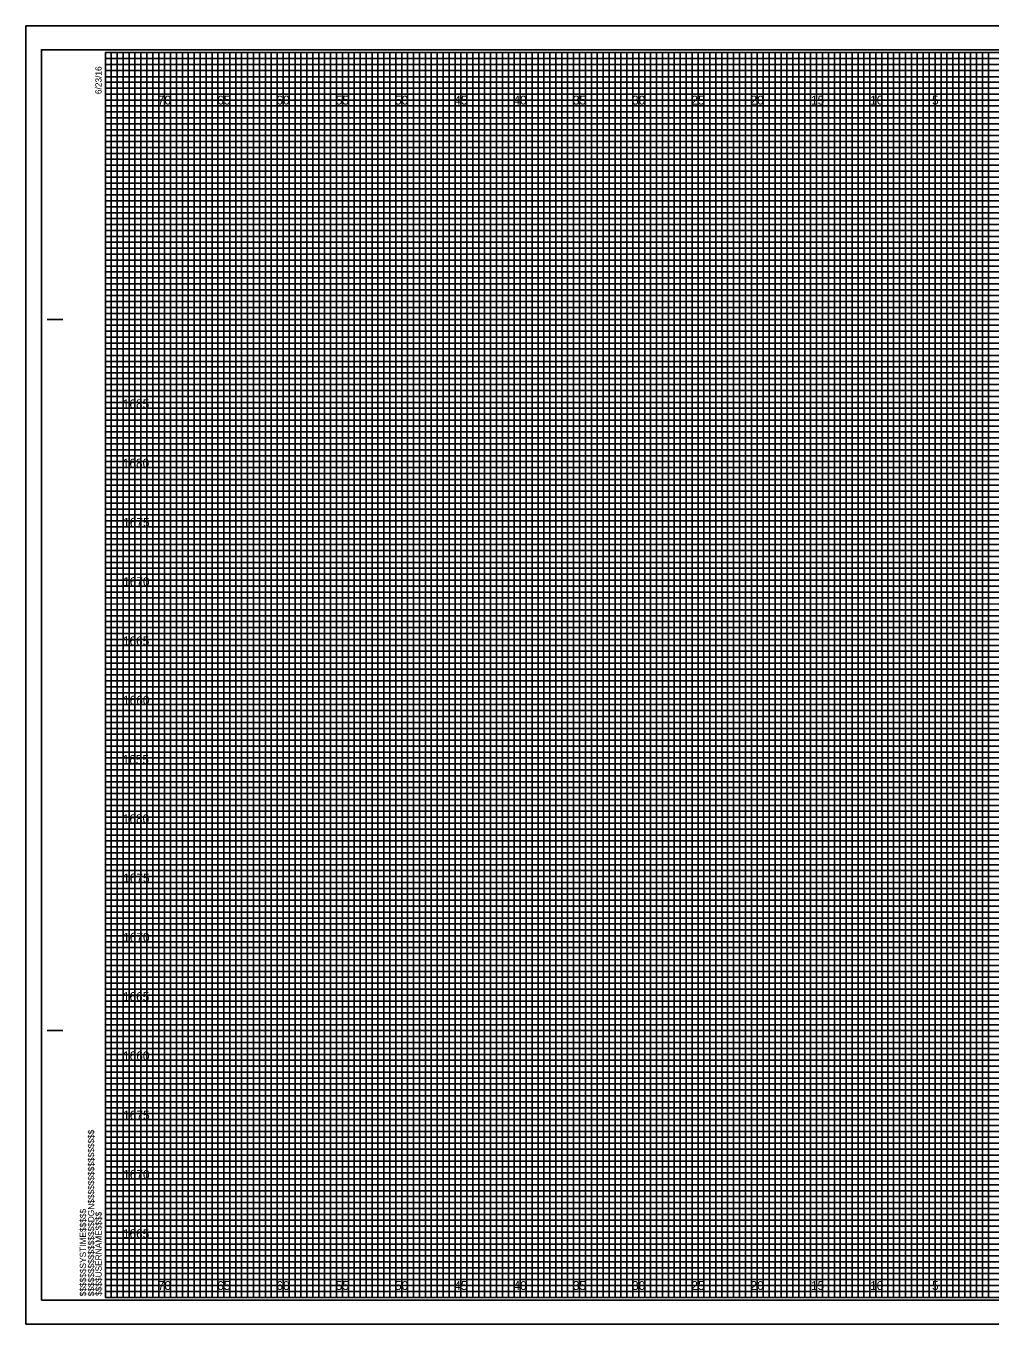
# Model space of a CAD drawing. Extents: x 172 to 723, y -2 to 439.
# Drawn here: x 172.3 to 253.6, y -2.3 to 107.3 of the extents above; entities that cross this region are included whole.
import ezdxf

# ---------------------------------------------------------------- set-up
doc = ezdxf.new("R2010")
doc.units = 0
for name, color, linetype in [('Prop XS Elevation Labels', 7, 'Continuous'), ('Prop XS Offset Labels', 7, 'Continuous'), ('Sheet Cross Section CELL', 7, 'Continuous'), ('Sheet Cross Section Grid Major CELL', 7, 'Continuous'), ('Sheet Cross Section Grid Middle CELL', 7, 'Continuous'), ('Sheet Cross Section Grid Minor 1 CELL', 7, 'Continuous'), ('Sheet Cross Section Grid Minor 2 CELL', 7, 'Continuous'), ('Sheet Cutting Line CELL', 7, 'Continuous'), ('Sheet DOT Grid CELL', 7, 'Continuous'), ('Sheet Plot Border Inside CELL', 7, 'Continuous'), ('Sheet Plot Border Outside CELL', 7, 'Continuous')]:
    doc.layers.add(name, color=color, linetype=linetype)

msp = doc.modelspace()

# ---------------------------------------------------------------- linework, layer by layer
at = {"layer": 'Sheet Cross Section CELL'}
for p, q in [((174.07, 82.5), (175.32, 82.5)), ((174.12, 82.5), (175.37, 82.5)), ((174.07, 22.5), (175.32, 22.5)), ((174.12, 22.5), (175.37, 22.5)), ((178.97, 0), (178.97, 0)), ((178.97, 0), (178.97, 0)), ((178.97, 0), (178.97, 0)), ((178.97, 0), (178.97, 0)), ((178.97, 0), (178.97, 0)), ((178.97, 0), (178.97, 0)), ((178.97, 0), (178.97, 0))]:
    msp.add_line(p, q, dxfattribs=at)
msp.add_lwpolyline([(338.97, 105), (178.97, 105), (178.97, 0), (338.97, 0)], close=True, dxfattribs=at)
at = {"layer": 'Sheet Cross Section Grid Major CELL'}
for p, q in [((183.97, 105), (178.97, 105)), ((183.97, 0), (183.97, 105)), ((193.97, 105), (188.97, 105)), ((188.97, 105), (188.97, 0)), ((193.97, 0), (193.97, 105)), ((203.97, 105), (198.97, 105)), ((198.97, 105), (198.97, 0)), ((203.97, 0), (203.97, 105)), ((213.97, 105), (208.97, 105)), ((208.97, 105), (208.97, 0)), ((213.97, 0), (213.97, 105)), ((223.97, 105), (218.97, 105)), ((218.97, 105), (218.97, 0)), ((223.97, 0), (223.97, 105)), ((233.97, 105), (228.97, 105)), ((228.97, 105), (228.97, 0)), ((233.97, 0), (233.97, 105)), ((243.97, 105), (238.97, 105)), ((238.97, 105), (238.97, 0)), ((243.97, 0), (243.97, 105)), ((253.97, 105), (248.97, 105)), ((248.97, 105), (248.97, 0)), ((188.97, 0), (183.97, 0)), ((198.97, 0), (193.97, 0)), ((208.97, 0), (203.97, 0)), ((218.97, 0), (213.97, 0)), ((228.97, 0), (223.97, 0)), ((238.97, 0), (233.97, 0)), ((248.97, 0), (243.97, 0))]:
    msp.add_line(p, q, dxfattribs=at)
for points in [[(178.97, 100), (338.97, 100), (338.97, 95), (178.97, 95)], [(178.97, 90), (338.97, 90), (338.97, 85), (178.97, 85)], [(178.97, 80), (338.97, 80), (338.97, 75), (178.97, 75)], [(178.97, 70), (338.97, 70), (338.97, 65), (178.97, 65)], [(178.97, 60), (338.97, 60), (338.97, 55), (178.97, 55)], [(178.97, 50), (338.97, 50), (338.97, 45), (178.97, 45)], [(178.97, 40), (338.97, 40), (338.97, 35), (178.97, 35)], [(178.97, 30), (338.97, 30), (338.97, 25), (178.97, 25)], [(178.97, 20), (338.97, 20), (338.97, 15), (178.97, 15)], [(178.97, 10), (338.97, 10), (338.97, 5), (178.97, 5)]]:
    msp.add_lwpolyline(points, dxfattribs=at)
at = {"layer": 'Sheet Cross Section Grid Middle CELL'}
for points in [[(178.97, 105), (181.47, 105), (181.47, 0), (186.47, 0), (186.47, 105), (191.47, 105), (191.47, 0), (196.47, 0), (196.47, 105), (201.47, 105), (201.47, 0), (206.47, 0), (206.47, 105), (211.47, 105), (211.47, 0), (216.47, 0), (216.47, 105), (221.47, 105), (221.47, 0), (226.47, 0), (226.47, 105), (231.47, 105), (231.47, 0), (236.47, 0), (236.47, 105), (241.47, 105), (241.47, 0), (246.47, 0), (246.47, 105), (251.47, 105), (251.47, 0), (256.47, 0)], [(178.97, 102.5), (316.47, 102.5)], [(178.97, 92.5), (338.97, 92.5), (338.97, 97.5), (178.97, 97.5)], [(178.97, 82.5), (338.97, 82.5), (338.97, 87.5), (178.97, 87.5)], [(178.97, 72.5), (338.97, 72.5), (338.97, 77.5), (178.97, 77.5)], [(178.97, 62.5), (338.97, 62.5), (338.97, 67.5), (178.97, 67.5)], [(178.97, 52.5), (338.97, 52.5), (338.97, 57.5), (178.97, 57.5)], [(178.97, 42.5), (338.97, 42.5), (338.97, 47.5), (178.97, 47.5)], [(178.97, 32.5), (338.97, 32.5), (338.97, 37.5), (178.97, 37.5)], [(178.97, 22.5), (338.97, 22.5), (338.97, 27.5), (178.97, 27.5)], [(178.97, 12.5), (338.97, 12.5), (338.97, 17.5), (178.97, 17.5)], [(178.97, 2.5), (338.97, 2.5), (338.97, 7.5), (178.97, 7.5)]]:
    msp.add_lwpolyline(points, dxfattribs=at)
at = {"layer": 'Sheet Cross Section Grid Minor 1 CELL'}
for p, q in [((178.97, 104.5), (308.97, 104.5)), ((308.97, 103.99), (178.97, 103.99)), ((178.97, 103.99), (178.97, 103.5)), ((178.97, 103.5), (308.97, 103.5)), ((308.97, 102.95), (178.97, 102.95)), ((178.97, 102.95), (178.97, 102)), ((178.97, 102), (338.97, 102))]:
    msp.add_line(p, q, dxfattribs=at)
for points in [[(178.97, 101.5), (313.97, 101.5), (338.97, 101.5), (338.97, 101), (178.97, 101)], [(178.97, 100.5), (338.97, 100.5), (338.97, 99.5), (178.97, 99.5)], [(178.97, 99), (338.97, 99), (338.97, 98.5), (178.97, 98.49)], [(178.97, 98), (338.97, 98), (338.97, 97), (178.97, 97)], [(178.97, 96.5), (338.97, 96.5), (338.97, 96), (178.97, 96)], [(178.97, 95.5), (338.97, 95.5), (338.97, 94.5), (178.97, 94.5)], [(178.97, 94), (338.97, 94), (338.97, 93.5), (178.97, 93.5)], [(178.97, 93), (338.97, 93), (338.97, 92), (178.97, 92)], [(178.97, 91.5), (338.97, 91.5), (338.97, 91), (178.97, 91)], [(178.97, 90.5), (338.97, 90.5), (338.97, 89.5), (178.97, 89.5)], [(178.97, 89), (338.97, 89), (338.97, 88.5), (178.97, 88.5)], [(178.97, 88), (338.97, 88), (338.97, 86.98), (338.97, 86.5), (338.97, 86), (178.97, 86)], [(178.97, 87), (338.97, 87), (338.97, 86.5), (178.97, 86.5)], [(178.97, 85.5), (338.97, 85.5), (338.97, 84.5), (178.97, 84.52)], [(178.97, 84.52), (338.97, 84.5), (338.97, 84), (178.97, 84)], [(178.97, 83.5), (338.97, 83.5), (338.97, 83), (178.97, 83)], [(178.97, 82), (338.97, 82), (338.97, 81.5), (178.97, 81.5)], [(178.97, 81), (338.97, 81), (338.97, 80.5), (178.97, 80.5)], [(178.94, 79.45), (338.97, 79.45), (338.97, 78.94), (178.94, 78.94)], [(178.97, 78.5), (338.97, 78.5), (338.97, 78), (178.97, 78)], [(178.97, 77), (338.97, 77), (338.97, 76.5), (178.97, 76.5)], [(178.97, 76), (338.97, 76), (338.97, 75.5), (178.97, 75.5)], [(178.97, 74.5), (338.97, 74.5), (338.97, 74), (178.97, 74)], [(178.97, 73.5), (338.97, 73.5), (338.97, 73), (178.97, 73)], [(178.97, 72), (338.97, 72), (338.97, 71.5), (178.97, 71.5)], [(178.97, 71), (338.97, 71), (338.97, 70.5), (178.97, 70.5)], [(178.97, 69.5), (338.97, 69.5), (338.97, 68.99), (178.97, 69)], [(178.97, 68.5), (338.97, 68.5), (338.97, 68), (178.97, 68)], [(178.97, 67), (338.97, 67), (338.97, 66.5), (178.97, 66.5)], [(178.97, 66), (338.97, 66), (338.97, 65.5), (178.97, 65.5)], [(178.97, 64.5), (338.97, 64.5), (338.97, 64), (178.97, 64)], [(178.97, 63.5), (338.97, 63.5), (338.97, 63), (178.97, 63)], [(178.97, 62), (338.97, 62), (338.97, 61.5), (178.97, 61.5)], [(178.97, 61), (338.97, 61), (338.97, 60.5), (178.97, 60.5)], [(178.97, 59.5), (338.97, 59.5), (338.97, 59), (178.97, 59)], [(178.97, 58.5), (339.01, 58.45), (338.97, 58), (178.97, 58)], [(178.97, 57), (338.97, 57), (338.97, 56.5), (178.97, 56.5)], [(178.97, 56), (338.97, 56), (338.97, 55.5), (178.97, 55.5)], [(178.97, 54.5), (338.97, 54.5), (338.97, 54), (178.97, 54)], [(178.97, 53.5), (338.97, 53.5), (338.97, 53), (178.97, 53)], [(178.97, 52), (338.97, 52), (338.97, 51.5), (178.97, 51.5)], [(178.97, 51), (338.97, 51), (338.97, 50.5), (178.97, 50.5)], [(178.97, 49.5), (338.97, 49.5), (338.97, 49), (178.97, 49)], [(178.97, 48.5), (338.97, 48.5), (338.97, 48), (178.97, 48)], [(178.97, 47), (338.97, 47), (338.97, 46.5), (178.97, 46.5)], [(178.97, 46), (338.97, 46), (338.97, 45.5), (178.97, 45.5)], [(178.97, 44.5), (338.97, 44.5), (338.97, 44), (178.97, 44)], [(178.97, 43.5), (338.97, 43.5), (338.97, 43), (178.97, 43)], [(178.97, 42), (338.97, 42), (338.97, 41.5), (178.97, 41.5)], [(178.97, 41), (338.97, 41), (338.97, 40.5), (178.97, 40.5)], [(178.97, 39.5), (338.97, 39.5), (338.97, 38.99), (178.97, 39)], [(178.97, 38.5), (338.97, 38.5), (338.97, 38), (178.97, 38)], [(178.97, 37), (338.97, 37), (338.97, 36.5), (178.97, 36.5)], [(178.97, 36), (338.97, 36), (338.97, 35.5), (178.97, 35.5)], [(178.97, 34.5), (338.97, 34.5), (338.97, 34), (178.97, 34)], [(178.97, 33.5), (338.97, 33.5), (338.97, 33), (178.97, 33)], [(178.97, 32), (338.97, 32), (338.97, 31.5), (178.97, 31.5)], [(178.97, 31), (338.97, 31), (338.97, 30.5), (178.97, 30.5)], [(178.97, 29.5), (338.97, 29.5), (338.97, 29), (178.97, 29)], [(178.97, 28.5), (339.01, 28.46), (338.97, 28), (178.97, 28)], [(178.97, 27), (338.97, 27), (338.97, 26.5), (178.97, 26.5)], [(178.97, 26), (338.97, 26), (338.97, 25.5), (178.97, 25.5)], [(178.97, 24.5), (338.97, 24.5), (338.97, 24), (178.97, 24)], [(178.97, 23.5), (338.97, 23.5), (338.97, 23), (178.97, 23)], [(178.97, 22), (338.97, 22), (338.97, 21.5), (178.97, 21.5)], [(178.97, 21), (338.97, 21), (338.97, 20.5), (178.97, 20.5)], [(178.97, 19.5), (338.97, 19.5), (338.97, 19), (178.97, 19)], [(178.97, 18.5), (338.97, 18.5), (338.97, 18), (178.97, 18)], [(178.97, 17), (338.97, 17), (338.97, 16.5), (178.97, 16.5)], [(178.97, 16), (338.97, 16), (338.97, 15.5), (178.97, 15.5)], [(178.97, 14.5), (338.97, 14.5), (338.97, 14), (178.97, 14)], [(178.97, 13.5), (338.97, 13.5), (338.97, 13), (178.97, 13)], [(178.97, 12), (338.97, 12), (338.97, 11.5), (178.97, 11.5)], [(178.97, 11), (338.97, 11), (338.97, 10.5), (178.97, 10.5)], [(178.97, 9.5), (338.97, 9.5), (338.97, 9), (178.97, 9)], [(178.97, 8.5), (338.97, 8.5), (338.97, 8), (178.97, 8)], [(178.97, 7), (338.97, 7), (338.97, 6.5), (178.97, 6.5)], [(178.97, 6), (338.97, 6), (338.97, 5.5), (178.97, 5.5)], [(178.97, 4.5), (338.97, 4.5), (338.97, 4), (178.97, 4)], [(178.97, 3.5), (338.97, 3.5), (338.97, 3), (178.97, 3)], [(178.97, 2), (338.97, 2), (338.97, 1.5), (178.97, 1.5)], [(178.97, 1), (338.97, 1), (338.97, 0.5), (178.97, 0.5)]]:
    msp.add_lwpolyline(points, dxfattribs=at)
at = {"layer": 'Sheet Cross Section Grid Minor 2 CELL'}
for points in [[(178.97, 0), (179.47, 0), (179.47, 105), (179.97, 105), (179.97, 0)], [(179.97, 0), (180.47, 0), (180.47, 105), (180.97, 105), (180.97, 0)], [(181.47, 0), (181.97, 0), (181.97, 105), (182.47, 105), (182.47, 0)], [(182.47, 0), (182.97, 0), (182.97, 105), (183.47, 105), (183.47, 0)], [(183.97, 0), (184.47, 0), (184.47, 105), (184.97, 105), (184.97, 0)], [(184.97, 0), (185.47, 0), (185.47, 105), (185.97, 105), (185.97, 0)], [(186.47, 0), (186.97, 0), (186.97, 105), (187.47, 105), (187.47, 0)], [(187.47, 0), (187.97, 0), (187.97, 105), (188.47, 105), (188.47, 0)], [(188.97, 0), (189.47, 0), (189.47, 105), (189.97, 105), (189.97, 0)], [(189.97, 0), (190.47, 0), (190.47, 105), (190.97, 105), (190.97, 0)], [(191.47, 0), (191.97, 0), (191.97, 105), (192.47, 105), (192.47, 0)], [(192.47, 0), (192.97, 0), (192.97, 105), (193.47, 105), (193.47, 0)], [(193.97, 0), (194.47, 0), (194.47, 105), (194.97, 105), (194.97, 0)], [(194.97, 0), (195.47, 0), (195.47, 105), (195.97, 105), (195.97, 0)], [(196.47, 0), (196.97, 0), (196.97, 105), (197.47, 105), (197.47, 0)], [(197.47, 0), (197.97, 0), (197.97, 105), (198.47, 105), (198.47, 0)], [(198.97, 0), (199.47, 0), (199.47, 105), (199.97, 105), (199.97, 0)], [(199.97, 0), (200.47, 0), (200.47, 105), (200.97, 105), (200.97, 0)], [(201.47, 0), (201.97, 0), (201.97, 105), (202.47, 105), (202.47, 0)], [(202.47, 0), (202.97, 0), (202.97, 105), (203.47, 105), (203.47, 0)], [(203.97, 0), (204.47, 0), (204.47, 105), (204.97, 105), (204.97, 0)], [(204.97, 0), (205.47, 0), (205.47, 105), (205.97, 105), (205.97, 0)], [(206.47, 0), (206.97, 0), (206.97, 105), (207.47, 105), (207.47, 0)], [(207.47, 0), (207.97, 0), (207.97, 105), (208.47, 105), (208.47, 0)], [(208.97, 0), (209.47, 0), (209.47, 105), (209.97, 105), (209.97, 0)], [(209.97, 0), (210.47, 0), (210.47, 105), (210.97, 105), (210.97, 0)], [(211.47, 0), (211.97, 0), (211.97, 105), (212.47, 105), (212.47, 0)], [(212.47, 0), (212.97, 0), (212.97, 105), (213.47, 105), (213.47, 0)], [(213.97, 0), (214.47, 0), (214.47, 105), (214.97, 105), (214.97, 0)], [(214.97, 0), (215.47, 0), (215.47, 105), (215.97, 105), (215.97, 0)], [(216.47, 0), (216.97, 0), (216.97, 105), (217.47, 105), (217.47, 0)], [(217.47, 0), (217.97, 0), (217.97, 105), (218.47, 105), (218.47, 0)], [(218.97, 0), (219.47, 0), (219.47, 105), (219.97, 105), (219.97, 0)], [(219.97, 0), (220.47, 0), (220.47, 105), (220.97, 105), (220.97, 0)], [(221.47, 0), (221.97, 0), (221.97, 105), (222.47, 105), (222.47, 0)], [(222.47, 0), (222.97, 0), (222.97, 105), (223.47, 105), (223.47, 0)], [(223.97, 0), (224.47, 0), (224.47, 105), (224.97, 105), (224.97, 0)], [(224.97, 0), (225.47, 0), (225.47, 105), (225.97, 105), (225.97, 0)], [(226.47, 0), (226.97, 0), (226.97, 105), (227.47, 105), (227.47, 0)], [(227.47, 0), (227.97, 0), (227.97, 105), (228.47, 105), (228.47, 0)], [(228.97, 0), (229.47, 0), (229.47, 105), (229.97, 105), (229.97, 0)], [(229.97, 0), (230.47, 0), (230.47, 105), (230.97, 105), (230.97, 0)], [(231.47, 0), (231.97, 0), (231.97, 105), (232.47, 105), (232.47, 0)], [(232.47, 0), (232.97, 0), (232.97, 105), (233.47, 105), (233.47, 0)], [(233.97, 0), (234.47, 0), (234.47, 105), (234.97, 105), (234.97, 0)], [(234.97, 0), (235.47, 0), (235.47, 105), (235.97, 105), (235.97, 0)], [(236.47, 0), (236.97, 0), (236.97, 105), (237.47, 105), (237.47, 0)], [(237.47, 0), (237.97, 0), (237.97, 105), (238.47, 105), (238.47, 0)], [(238.97, 0), (239.47, 0), (239.47, 105), (239.97, 105), (239.97, 0)], [(239.97, 0), (240.47, 0), (240.47, 105), (240.97, 105), (240.97, 0)], [(241.47, 0), (241.97, 0), (241.97, 105), (242.47, 105), (242.47, 0)], [(242.47, 0), (242.97, 0), (242.97, 105), (243.47, 105), (243.47, 0)], [(243.97, 0), (244.47, 0), (244.47, 105), (244.97, 105), (244.97, 0)], [(244.97, 0), (245.47, 0), (245.47, 105), (245.97, 105), (245.97, 0)], [(246.47, 0), (246.97, 0), (246.97, 105), (247.47, 105), (247.47, 0)], [(247.47, 0), (247.97, 0), (247.97, 105), (248.47, 105), (248.47, 0)], [(248.97, 0), (249.47, 0), (249.47, 105), (249.97, 105), (249.97, 0)], [(249.97, 0), (250.47, 0), (250.47, 105), (250.97, 105), (250.97, 0)], [(251.47, 0), (251.97, 0), (251.97, 105), (252.47, 105), (252.47, 0)], [(252.47, 0), (252.97, 0), (252.97, 105), (253.47, 105), (253.47, 0)]]:
    msp.add_lwpolyline(points, dxfattribs=at)
at = {"layer": 'Sheet Cutting Line CELL'}
for p, q in [((340.62, 107.25), (172.27, 107.25)), ((172.27, 107.25), (172.27, -2.25)), ((172.27, -2.25), (340.62, -2.25))]:
    msp.add_line(p, q, dxfattribs=at)
at = {"layer": 'Sheet DOT Grid CELL'}
for p, q in [((183.97, 0), (183.97, 105)), ((188.97, 0), (188.97, 105)), ((193.97, 0), (193.97, 105)), ((198.97, 0), (198.97, 105)), ((203.97, 0), (203.97, 105)), ((208.97, 0), (208.97, 105)), ((213.97, 0), (213.97, 105)), ((218.97, 0), (218.97, 105)), ((223.97, 0), (223.97, 105)), ((228.97, 0), (228.97, 105)), ((233.97, 0), (233.97, 105)), ((238.97, 0), (238.97, 105)), ((243.97, 0), (243.97, 105)), ((248.97, 0), (248.97, 105)), ((178.97, 100), (338.97, 100)), ((178.97, 95), (338.97, 95)), ((178.97, 90), (338.97, 90)), ((178.97, 85), (338.97, 85)), ((178.97, 80), (338.97, 80)), ((178.97, 75), (338.97, 75)), ((178.97, 70), (338.97, 70)), ((178.97, 65), (338.97, 65)), ((178.97, 60), (338.97, 60)), ((178.97, 55), (338.97, 55)), ((178.97, 50), (338.97, 50)), ((178.97, 45), (338.97, 45)), ((178.97, 40), (338.97, 40)), ((178.97, 35), (338.97, 35)), ((178.97, 30), (338.97, 30)), ((178.97, 25), (338.97, 25)), ((178.97, 20), (338.97, 20)), ((178.97, 15), (338.97, 15)), ((178.97, 10), (338.97, 10)), ((178.97, 5), (338.97, 5))]:
    msp.add_line(p, q, dxfattribs=at)
at = {"layer": 'Sheet Plot Border Inside CELL'}
msp.add_lwpolyline([(173.57, -0.25), (340.17, -0.25), (340.17, 105.25), (173.57, 105.25)], close=True, dxfattribs=at)
at = {"layer": 'Sheet Plot Border Outside CELL'}
msp.add_lwpolyline([(172.27, -2.25), (340.62, -2.25), (340.62, 107.25), (172.27, 107.25)], close=True, dxfattribs=at)

# ---------------------------------------------------------------- texts
at = {"layer": 'Prop XS Elevation Labels'}
for s, p in [('1685', (180.44, 75)), ('1680', (180.44, 70)), ('1675', (180.47, 65)), ('1670', (180.47, 60)), ('1665', (180.45, 55)), ('1660', (180.46, 50)), ('1655', (180.42, 45)), ('1680', (180.44, 40)), ('1675', (180.47, 35)), ('1670', (180.47, 30)), ('1665', (180.45, 25)), ('1660', (180.46, 20)), ('1675', (180.47, 15)), ('1670', (180.47, 10)), ('1665', (180.45, 5))]:
    msp.add_text(s, height=0.75, dxfattribs=at).set_placement(p)
at = {"layer": 'Prop XS Offset Labels'}
for s, p in [('70', (183.4, 100.62)), ('65', (188.41, 100.62)), ('60', (193.4, 100.62)), ('55', (198.41, 100.62)), ('50', (203.4, 100.62)), ('45', (208.41, 100.62)), ('40', (213.4, 100.62)), ('35', (218.41, 100.62)), ('30', (223.4, 100.62)), ('25', (228.41, 100.62)), ('20', (233.4, 100.62)), ('15', (238.5, 100.62)), ('10', (243.49, 100.62)), ('5', (248.71, 100.62)), ('70', (183.4, 0.62)), ('65', (188.41, 0.62)), ('60', (193.4, 0.62)), ('55', (198.41, 0.62)), ('50', (203.4, 0.62)), ('45', (208.41, 0.62)), ('40', (213.4, 0.62)), ('35', (218.41, 0.62)), ('30', (223.4, 0.62)), ('25', (228.41, 0.62)), ('20', (233.4, 0.62)), ('15', (238.5, 0.62)), ('10', (243.49, 0.62)), ('5', (248.71, 0.62))]:
    msp.add_text(s, height=0.75, dxfattribs=at).set_placement(p)
at = {"layer": 'Sheet Cross Section CELL'}
for s, p in [('6/23/16', (178.65, 101.5)), ('$$$$$$$$$$$$$$$$DGN$$$$$$$$$$$$$$$$', (178.03, 0.09)), ('$$$$$$SYSTIME$$$$$', (177.34, 0.09)), ('$$$$USERNAME$$$$', (178.66, 0.12))]:
    msp.add_text(s, height=0.525, rotation=90, dxfattribs=at).set_placement(p)

doc.saveas('drawing.dxf')
